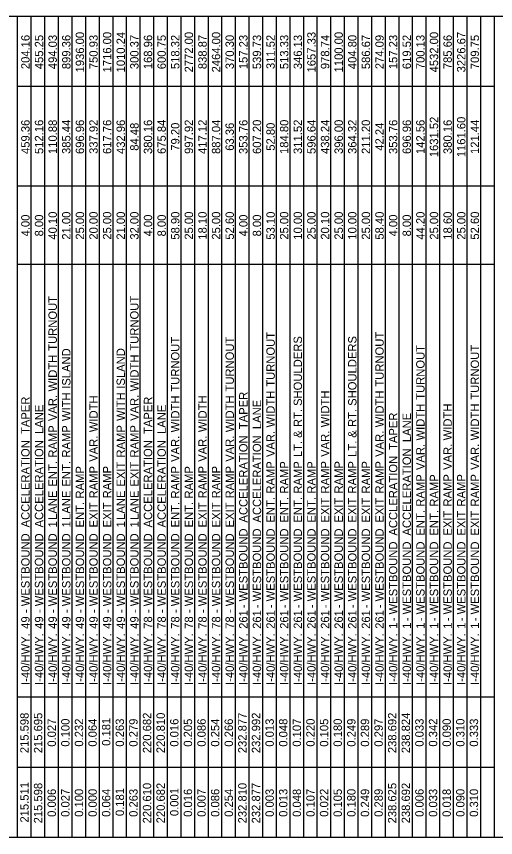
# Model space of a CAD drawing. Extents: x 2261867 to 2275370, y -3124789 to -3122260.
# Drawn here: x 2267289 to 2267632, y -3123394 to -3122807 of the extents above; entities that cross this region are included whole.
import ezdxf

# ---------------------------------------------------------------- set-up
doc = ezdxf.new("R2010")
doc.units = 0
doc.layers.add('Default', color=7, linetype='Continuous')

msp = doc.modelspace()

# ---------------------------------------------------------------- linework, layer by layer
at = {"layer": 'Default'}
for p, q in [((2268157.39, -3122806.82), (2267016.64, -3122806.82)), ((2268157.39, -3122806.82), (2267016.64, -3122806.82)), ((2267289.64, -3123394.26), (2267289.64, -3122806.82)), ((2267299.39, -3123394.26), (2267299.39, -3122806.82)), ((2267299.39, -3122857.03), (2267299.39, -3122806.82)), ((2267309.14, -3123394.26), (2267309.14, -3122806.82)), ((2267309.14, -3122857.03), (2267309.14, -3122806.82)), ((2267318.89, -3123394.26), (2267318.89, -3122806.82)), ((2267318.89, -3122857.03), (2267318.89, -3122806.82)), ((2267328.64, -3123394.26), (2267328.64, -3122806.82)), ((2267328.64, -3122857.03), (2267328.64, -3122806.82)), ((2267338.39, -3123394.26), (2267338.39, -3122806.82)), ((2267338.39, -3122857.03), (2267338.39, -3122806.82)), ((2267348.14, -3123394.26), (2267348.14, -3122806.82)), ((2267348.14, -3122857.03), (2267348.14, -3122806.82)), ((2267357.89, -3123394.26), (2267357.89, -3122806.82)), ((2267357.89, -3122857.03), (2267357.89, -3122806.82)), ((2267367.64, -3123394.26), (2267367.64, -3122806.82)), ((2267367.64, -3122857.03), (2267367.64, -3122806.82)), ((2267377.39, -3123394.26), (2267377.39, -3122806.82)), ((2267377.39, -3122857.03), (2267377.39, -3122806.82)), ((2267387.14, -3123394.26), (2267387.14, -3122806.82)), ((2267387.14, -3122857.03), (2267387.14, -3122806.82)), ((2267396.89, -3123394.26), (2267396.89, -3122806.82)), ((2267396.89, -3122857.03), (2267396.89, -3122806.82)), ((2267406.64, -3123394.26), (2267406.64, -3122806.82)), ((2267406.64, -3122857.03), (2267406.64, -3122806.82)), ((2267416.39, -3123394.26), (2267416.39, -3122806.82)), ((2267416.39, -3122857.03), (2267416.39, -3122806.82)), ((2267426.14, -3123394.26), (2267426.14, -3122806.82)), ((2267426.14, -3122857.03), (2267426.14, -3122806.82)), ((2267435.89, -3123394.26), (2267435.89, -3122806.82)), ((2267435.89, -3122857.03), (2267435.89, -3122806.82)), ((2267445.64, -3123394.26), (2267445.64, -3122806.82)), ((2267445.64, -3122857.03), (2267445.64, -3122806.82)), ((2267455.39, -3123394.26), (2267455.39, -3122806.82)), ((2267455.39, -3122857.03), (2267455.39, -3122806.82)), ((2267465.14, -3123394.26), (2267465.14, -3122806.82)), ((2267465.14, -3122857.03), (2267465.14, -3122806.82)), ((2267474.89, -3123394.26), (2267474.89, -3122806.82)), ((2267474.89, -3122857.03), (2267474.89, -3122806.82)), ((2267484.64, -3123394.26), (2267484.64, -3122806.82)), ((2267484.64, -3122857.03), (2267484.64, -3122806.82)), ((2267494.39, -3123394.26), (2267494.39, -3122806.82)), ((2267494.39, -3122857.03), (2267494.39, -3122806.82)), ((2267504.14, -3123394.26), (2267504.14, -3122806.82)), ((2267504.14, -3122857.03), (2267504.14, -3122806.82)), ((2267513.89, -3123394.26), (2267513.89, -3122806.82)), ((2267513.89, -3122857.03), (2267513.89, -3122806.82)), ((2267523.64, -3123394.26), (2267523.64, -3122806.82)), ((2267523.64, -3122857.03), (2267523.64, -3122806.82)), ((2267533.39, -3123394.26), (2267533.39, -3122806.82)), ((2267533.39, -3122857.03), (2267533.39, -3122806.82)), ((2267543.14, -3123394.26), (2267543.14, -3122806.82)), ((2267543.14, -3122857.03), (2267543.14, -3122806.82)), ((2267552.89, -3123394.26), (2267552.89, -3122806.82)), ((2267552.89, -3122857.03), (2267552.89, -3122806.82)), ((2267562.64, -3123394.26), (2267562.64, -3122806.82)), ((2267562.64, -3122857.03), (2267562.64, -3122806.82)), ((2267572.39, -3123394.26), (2267572.39, -3122806.82)), ((2267572.39, -3122857.03), (2267572.39, -3122806.82)), ((2267582.14, -3123394.26), (2267582.14, -3122806.82)), ((2267582.14, -3122857.03), (2267582.14, -3122806.82)), ((2267591.89, -3123394.26), (2267591.89, -3122806.82)), ((2267591.89, -3122857.03), (2267591.89, -3122806.82)), ((2267601.64, -3123394.26), (2267601.64, -3122806.82)), ((2267601.64, -3122857.03), (2267601.64, -3122806.82)), ((2267611.39, -3123394.26), (2267611.39, -3122806.82)), ((2267611.39, -3122857.03), (2267611.39, -3122806.82)), ((2267621.14, -3123394.26), (2267621.14, -3122806.82)), ((2267621.14, -3122857.03), (2267621.14, -3122806.82)), ((2267630.89, -3122857.03), (2267630.89, -3122806.82)), ((2267630.89, -3123394.26), (2267630.89, -3122806.82)), ((2267289.64, -3122928.21), (2267289.64, -3122857.03)), ((2267630.89, -3122857.03), (2267289.64, -3122857.03)), ((2267630.89, -3122857.03), (2267289.64, -3122857.03)), ((2267299.39, -3122928.21), (2267299.39, -3122857.03)), ((2267309.14, -3122928.21), (2267309.14, -3122857.03)), ((2267318.89, -3122928.21), (2267318.89, -3122857.03)), ((2267328.64, -3122928.21), (2267328.64, -3122857.03)), ((2267338.39, -3122928.21), (2267338.39, -3122857.03)), ((2267348.14, -3122928.21), (2267348.14, -3122857.03)), ((2267357.89, -3122928.21), (2267357.89, -3122857.03)), ((2267367.64, -3122928.21), (2267367.64, -3122857.03)), ((2267377.39, -3122928.21), (2267377.39, -3122857.03)), ((2267387.14, -3122928.21), (2267387.14, -3122857.03)), ((2267396.89, -3122928.21), (2267396.89, -3122857.03)), ((2267406.64, -3122928.21), (2267406.64, -3122857.03)), ((2267416.39, -3122928.21), (2267416.39, -3122857.03)), ((2267426.14, -3122928.21), (2267426.14, -3122857.03)), ((2267435.89, -3122928.21), (2267435.89, -3122857.03)), ((2267445.64, -3122928.21), (2267445.64, -3122857.03)), ((2267455.39, -3122928.21), (2267455.39, -3122857.03)), ((2267465.14, -3122928.21), (2267465.14, -3122857.03)), ((2267474.89, -3122928.21), (2267474.89, -3122857.03)), ((2267484.64, -3122928.21), (2267484.64, -3122857.03)), ((2267494.39, -3122928.21), (2267494.39, -3122857.03)), ((2267504.14, -3122928.21), (2267504.14, -3122857.03)), ((2267513.89, -3122928.21), (2267513.89, -3122857.03)), ((2267523.64, -3122928.21), (2267523.64, -3122857.03)), ((2267533.39, -3122928.21), (2267533.39, -3122857.03)), ((2267543.14, -3122928.21), (2267543.14, -3122857.03)), ((2267552.89, -3122928.21), (2267552.89, -3122857.03)), ((2267562.64, -3122928.21), (2267562.64, -3122857.03)), ((2267572.39, -3122928.21), (2267572.39, -3122857.03)), ((2267582.14, -3122984.27), (2267582.14, -3122857.03)), ((2267591.89, -3122984.27), (2267591.89, -3122857.03)), ((2267601.64, -3122984.27), (2267601.64, -3122857.03)), ((2267611.39, -3122984.27), (2267611.39, -3122857.03)), ((2267621.14, -3122984.27), (2267621.14, -3122857.03)), ((2267630.89, -3122984.27), (2267630.89, -3122857.03)), ((2267289.64, -3122984.27), (2267289.64, -3122928.21)), ((2267630.89, -3122928.21), (2267289.64, -3122928.21)), ((2267630.89, -3122928.21), (2267289.64, -3122928.21)), ((2267630.89, -3122984.27), (2267289.64, -3122984.27)), ((2267630.89, -3122984.27), (2267289.64, -3122984.27)), ((2267630.89, -3123394.26), (2267630.89, -3122984.27)), ((2267289.64, -3123394.26), (2267289.64, -3123293.83)), ((2267630.89, -3123293.83), (2267289.64, -3123293.83)), ((2267630.89, -3123293.83), (2267289.64, -3123293.83)), ((2267630.89, -3123344.05), (2267289.64, -3123344.05)), ((2267630.89, -3123344.05), (2267299.39, -3123344.05)), ((2268157.39, -3123394.26), (2267016.64, -3123394.26)), ((2268157.39, -3123394.26), (2267016.64, -3123394.26))]:
    msp.add_line(p, q, dxfattribs=at)

# ---------------------------------------------------------------- texts
for s, p in [('204.16', (2267298.19, -3122844.55)), ('455.25', (2267307.94, -3122844.57)), ('494.03', (2267317.69, -3122844.55)), ('899.36', (2267327.44, -3122844.55)), ('1936.00', (2267337.19, -3122846.87)), ('750.93', (2267346.94, -3122844.55)), ('1716.00', (2267356.69, -3122846.87)), ('1010.24', (2267366.44, -3122846.87)), ('300.37', (2267376.19, -3122844.55)), ('168.96', (2267385.94, -3122844.55)), ('600.75', (2267395.69, -3122844.57)), ('518.32', (2267405.44, -3122844.52)), ('2772.00', (2267415.19, -3122846.87)), ('838.87', (2267424.94, -3122844.55)), ('2464.00', (2267434.69, -3122846.87)), ('370.30', (2267444.44, -3122844.54)), ('157.23', (2267454.19, -3122844.55)), ('539.73', (2267463.94, -3122844.55)), ('311.52', (2267473.69, -3122844.52)), ('513.33', (2267483.44, -3122844.55)), ('346.13', (2267493.19, -3122844.55)), ('1657.33', (2267502.94, -3122846.88)), ('978.74', (2267512.69, -3122844.54)), ('1100.00', (2267522.44, -3122846.87)), ('404.80', (2267532.19, -3122844.54)), ('586.67', (2267541.94, -3122844.55)), ('274.09', (2267551.69, -3122844.56)), ('157.23', (2267561.44, -3122844.55)), ('619.52', (2267571.19, -3122844.52)), ('700.13', (2267580.94, -3122844.55)), ('4532.00', (2267590.69, -3122846.87)), ('785.66', (2267600.44, -3122844.55)), ('3226.67', (2267610.19, -3122846.88)), ('709.75', (2267619.94, -3122844.57)), ('459.36', (2267298.19, -3122905.25)), ('512.16', (2267307.94, -3122905.25)), ('110.88', (2267317.69, -3122905.25)), ('385.44', (2267327.44, -3122905.23)), ('696.96', (2267337.19, -3122905.25)), ('337.92', (2267346.94, -3122905.21)), ('617.76', (2267356.69, -3122905.25)), ('432.96', (2267366.44, -3122905.25)), ('380.16', (2267385.94, -3122905.25)), ('675.84', (2267395.69, -3122905.23)), ('997.92', (2267415.19, -3122905.21)), ('417.12', (2267424.94, -3122905.21)), ('887.04', (2267434.69, -3122905.23)), ('353.76', (2267454.19, -3122905.25)), ('607.20', (2267463.94, -3122905.23)), ('184.80', (2267483.44, -3122905.23)), ('311.52', (2267493.19, -3122905.21)), ('596.64', (2267502.94, -3122905.23)), ('438.24', (2267512.69, -3122905.23)), ('396.00', (2267522.44, -3122905.23)), ('364.32', (2267532.19, -3122905.21)), ('211.20', (2267541.94, -3122905.23)), ('353.76', (2267561.44, -3122905.25)), ('696.96', (2267571.19, -3122905.25)), ('142.56', (2267580.94, -3122905.25)), ('1631.52', (2267590.69, -3122907.54)), ('380.16', (2267600.44, -3122905.25)), ('1161.60', (2267610.19, -3122907.56)), ('121.44', (2267619.94, -3122905.23)), ('84.48', (2267376.19, -3122902.92)), ('79.20', (2267405.44, -3122902.9)), ('63.36', (2267444.44, -3122902.92)), ('52.80', (2267473.69, -3122902.9)), ('42.24', (2267551.69, -3122902.9)), ('40.10', (2267317.69, -3122966.52)), ('21.00', (2267327.44, -3122966.52)), ('25.00', (2267337.19, -3122966.52)), ('20.00', (2267346.94, -3122966.52)), ('25.00', (2267356.69, -3122966.52)), ('21.00', (2267366.44, -3122966.52)), ('32.00', (2267376.19, -3122966.52)), ('58.90', (2267405.44, -3122966.52)), ('25.00', (2267415.19, -3122966.52)), ('18.10', (2267424.94, -3122966.52)), ('25.00', (2267434.69, -3122966.52)), ('52.60', (2267444.44, -3122966.52)), ('53.10', (2267473.69, -3122966.52)), ('25.00', (2267483.44, -3122966.52)), ('10.00', (2267493.19, -3122966.52)), ('25.00', (2267502.94, -3122966.52)), ('20.10', (2267512.69, -3122966.52)), ('25.00', (2267522.44, -3122966.52)), ('10.00', (2267532.19, -3122966.52)), ('25.00', (2267541.94, -3122966.52)), ('58.40', (2267551.69, -3122966.52)), ('44.20', (2267580.94, -3122966.52)), ('25.00', (2267590.69, -3122966.52)), ('18.60', (2267600.44, -3122966.52)), ('25.00', (2267610.19, -3122966.52)), ('52.60', (2267619.94, -3122966.52)), ('4.00', (2267298.19, -3122964.19)), ('8.00', (2267307.94, -3122964.19)), ('4.00', (2267385.94, -3122964.19)), ('8.00', (2267395.69, -3122964.19)), ('4.00', (2267454.19, -3122964.19)), ('8.00', (2267463.94, -3122964.19)), ('4.00', (2267561.44, -3122964.19)), ('8.00', (2267571.19, -3122964.19)), (' TURNOUT', (2267317.69, -3123048.23)), (' TURNOUT', (2267376.19, -3123048.13)), (' TURNOUT', (2267473.69, -3123073.97)), (' TURNOUT', (2267551.69, -3123073.87)), (' TURNOUT', (2267405.44, -3123077.46)), (' TURNOUT', (2267444.44, -3123077.36)), (' SHOULDERS', (2267493.19, -3123087.72)), (' SHOULDERS', (2267532.19, -3123087.62)), (' ISLAND', (2267327.44, -3123075.45)), (' ISLAND', (2267366.44, -3123075.35)), (' TURNOUT', (2267580.94, -3123083.29)), (' TURNOUT', (2267619.94, -3123083.19)), (' WIDTH', (2267317.69, -3123077.35)), (' WIDTH', (2267376.19, -3123077.25)), (' TAPER', (2267454.19, -3123104.27)), (' WIDTH', (2267473.69, -3123103.09)), (' WIDTH', (2267512.69, -3123102.99)), (' WIDTH', (2267551.69, -3123102.99)), (' TAPER', (2267298.19, -3123107.76)), (' VAR.', (2267317.69, -3123098.52)), (' WITH', (2267327.44, -3123098.52)), (' WIDTH', (2267346.94, -3123106.48)), (' WITH', (2267366.44, -3123098.42)), (' VAR.', (2267376.19, -3123098.42)), (' TAPER', (2267385.94, -3123107.76)), (' WIDTH', (2267405.44, -3123106.58)), (' WIDTH', (2267424.94, -3123106.48)), (' WIDTH', (2267444.44, -3123106.48)), (' LANE', (2267463.94, -3123104.27)), (' LANE', (2267307.94, -3123107.76)), (' LANE', (2267395.69, -3123107.76)), (' WIDTH', (2267580.94, -3123112.41)), (' WIDTH', (2267600.44, -3123112.31)), (' WIDTH', (2267619.94, -3123112.31)), (' RT.', (2267493.19, -3123102.82)), (' RT.', (2267532.19, -3123102.72)), (' TAPER', (2267561.44, -3123119.19)), (' LANE', (2267571.19, -3123113.59)), (' RAMP', (2267317.69, -3123124.7)), (' RAMP', (2267327.44, -3123124.7)), (' RAMP', (2267366.44, -3123124.6)), (' RAMP', (2267376.19, -3123124.6)), (' VAR.', (2267473.69, -3123124.26)), (' &', (2267493.19, -3123110.55)), (' VAR.', (2267512.69, -3123124.16)), (' &', (2267532.19, -3123110.45)), (' VAR.', (2267551.69, -3123124.16)), (' ACCELERATION', (2267298.19, -3123174.63)), (' ACCELERATION', (2267307.94, -3123174.63)), (' VAR.', (2267346.94, -3123127.65)), (' ACCELERATION', (2267385.94, -3123174.63)), (' ACCELERATION', (2267395.69, -3123174.63)), (' VAR.', (2267405.44, -3123127.75)), (' VAR.', (2267424.94, -3123127.65)), (' VAR.', (2267444.44, -3123127.65)), (' ACCELERATION', (2267454.19, -3123171.14)), (' ACCELERATION', (2267463.94, -3123171.14)), (' LT.', (2267493.19, -3123124.26)), (' LT.', (2267532.19, -3123124.16)), (' ACCELERATION', (2267571.19, -3123180.46)), (' VAR.', (2267580.94, -3123133.58)), (' VAR.', (2267600.44, -3123133.48)), (' VAR.', (2267619.94, -3123133.48)), (' ACCLERATION', (2267561.44, -3123180.46)), (' ENT.', (2267317.69, -3123145.4)), (' ENT.', (2267327.44, -3123145.4)), (' RAMP', (2267337.19, -3123153.93)), (' RAMP', (2267346.94, -3123153.83)), (' RAMP', (2267356.69, -3123153.83)), (' EXIT', (2267366.44, -3123145.4)), (' EXIT', (2267376.19, -3123145.4)), (' RAMP', (2267405.44, -3123153.93)), (' RAMP', (2267415.19, -3123153.93)), (' RAMP', (2267424.94, -3123153.83)), (' RAMP', (2267434.69, -3123153.83)), (' RAMP', (2267444.44, -3123153.83)), (' RAMP', (2267473.69, -3123150.44)), (' RAMP', (2267483.44, -3123150.44)), (' RAMP', (2267493.19, -3123150.44)), (' RAMP', (2267502.94, -3123150.44)), (' RAMP', (2267512.69, -3123150.34)), (' RAMP', (2267522.44, -3123150.34)), (' RAMP', (2267532.19, -3123150.34)), (' RAMP', (2267541.94, -3123150.34)), (' RAMP', (2267551.69, -3123150.34)), (' RAMP', (2267580.94, -3123159.76)), (' RAMP', (2267590.69, -3123159.76)), (' RAMP', (2267600.44, -3123159.66)), (' RAMP', (2267610.19, -3123159.66)), (' RAMP', (2267619.94, -3123159.66)), (' LANE', (2267317.69, -3123169.18)), (' LANE', (2267327.44, -3123169.18)), (' LANE', (2267366.44, -3123169.18)), (' LANE', (2267376.19, -3123169.18)), (' ENT.', (2267473.69, -3123171.14)), (' ENT.', (2267483.44, -3123171.14)), (' ENT.', (2267493.19, -3123171.14)), (' ENT.', (2267502.94, -3123171.14)), (' EXIT', (2267512.69, -3123171.14)), (' EXIT', (2267522.44, -3123171.14)), (' EXIT', (2267532.19, -3123171.14)), (' EXIT', (2267541.94, -3123171.14)), (' EXIT', (2267551.69, -3123171.14)), (' ENT.', (2267337.19, -3123174.63)), (' EXIT', (2267346.94, -3123174.63)), (' EXIT', (2267356.69, -3123174.63)), (' ENT.', (2267405.44, -3123174.63)), (' ENT.', (2267415.19, -3123174.63)), (' EXIT', (2267424.94, -3123174.63)), (' EXIT', (2267434.69, -3123174.63)), (' EXIT', (2267444.44, -3123174.63)), (' ENT.', (2267580.94, -3123180.46)), (' ENT.', (2267590.69, -3123180.46)), (' EXIT', (2267600.44, -3123180.46)), (' EXIT', (2267610.19, -3123180.46)), (' EXIT', (2267619.94, -3123180.46)), (' 1', (2267317.69, -3123174.63)), (' 1', (2267327.44, -3123174.63)), (' 1', (2267366.44, -3123174.63)), (' 1', (2267376.19, -3123174.63)), (' WESTBOUND', (2267454.19, -3123227.51)), (' WESTBOUND', (2267463.94, -3123227.51)), (' WESTBOUND', (2267473.69, -3123227.51)), (' WESTBOUND', (2267483.44, -3123227.51)), (' WESTBOUND', (2267493.19, -3123227.51)), (' WESTBOUND', (2267502.94, -3123227.51)), (' WESTBOUND', (2267512.69, -3123227.51)), (' WESTBOUND', (2267522.44, -3123227.51)), (' WESTBOUND', (2267532.19, -3123227.51)), (' WESTBOUND', (2267541.94, -3123227.51)), (' WESTBOUND', (2267551.69, -3123227.51)), (' WESTBOUND', (2267298.19, -3123231)), (' WESTBOUND', (2267307.94, -3123231)), (' WESTBOUND', (2267317.69, -3123231)), (' WESTBOUND', (2267327.44, -3123231)), (' WESTBOUND', (2267337.19, -3123231)), (' WESTBOUND', (2267346.94, -3123231)), (' WESTBOUND', (2267356.69, -3123231)), (' WESTBOUND', (2267366.44, -3123231)), (' WESTBOUND', (2267376.19, -3123231)), (' WESTBOUND', (2267385.94, -3123231)), (' WESTBOUND', (2267395.69, -3123231)), (' WESTBOUND', (2267405.44, -3123231)), (' WESTBOUND', (2267415.19, -3123231)), (' WESTBOUND', (2267424.94, -3123231)), (' WESTBOUND', (2267434.69, -3123231)), (' WESTBOUND', (2267444.44, -3123231)), (' WESTBOUND', (2267561.44, -3123236.83)), (' WESTBOUND', (2267571.19, -3123236.83)), (' WESTBOUND', (2267580.94, -3123236.83)), (' WESTBOUND', (2267590.69, -3123236.83)), (' WESTBOUND', (2267600.44, -3123236.83)), (' WESTBOUND', (2267610.19, -3123236.83)), (' WESTBOUND', (2267619.94, -3123236.83)), (' -', (2267454.19, -3123232.37)), (' -', (2267463.94, -3123232.37)), (' -', (2267473.69, -3123232.37)), (' -', (2267483.44, -3123232.37)), (' -', (2267493.19, -3123232.37)), (' -', (2267502.94, -3123232.37)), (' -', (2267512.69, -3123232.37)), (' -', (2267522.44, -3123232.37)), (' -', (2267532.19, -3123232.37)), (' -', (2267541.94, -3123232.37)), (' -', (2267551.69, -3123232.37)), (' -', (2267298.19, -3123235.86)), (' -', (2267307.94, -3123235.86)), (' -', (2267317.69, -3123235.86)), (' -', (2267327.44, -3123235.86)), (' -', (2267337.19, -3123235.86)), (' -', (2267346.94, -3123235.86)), (' -', (2267356.69, -3123235.86)), (' -', (2267366.44, -3123235.86)), (' -', (2267376.19, -3123235.86)), (' -', (2267385.94, -3123235.86)), (' -', (2267395.69, -3123235.86)), (' -', (2267405.44, -3123235.86)), (' -', (2267415.19, -3123235.86)), (' -', (2267424.94, -3123235.86)), (' -', (2267434.69, -3123235.86)), (' -', (2267444.44, -3123235.86)), (' 261', (2267454.19, -3123247.14)), (' 261', (2267463.94, -3123247.14)), (' 261', (2267473.69, -3123247.14)), (' 261', (2267483.44, -3123247.14)), (' 261', (2267493.19, -3123247.14)), (' 261', (2267502.94, -3123247.14)), (' 261', (2267512.69, -3123247.14)), (' 261', (2267522.44, -3123247.14)), (' 261', (2267532.19, -3123247.14)), (' 261', (2267541.94, -3123247.14)), (' 261', (2267551.69, -3123247.14)), (' 49', (2267298.19, -3123247.14)), (' 49', (2267307.94, -3123247.14)), (' 49', (2267317.69, -3123247.14)), (' 49', (2267327.44, -3123247.14)), (' 49', (2267337.19, -3123247.14)), (' 49', (2267346.94, -3123247.14)), (' 49', (2267356.69, -3123247.14)), (' 49', (2267366.44, -3123247.14)), (' 49', (2267376.19, -3123247.14)), (' 78', (2267385.94, -3123247.14)), (' 78', (2267395.69, -3123247.14)), (' 78', (2267405.44, -3123247.14)), (' 78', (2267415.19, -3123247.14)), (' 78', (2267424.94, -3123247.14)), (' 78', (2267434.69, -3123247.14)), (' 78', (2267444.44, -3123247.14)), (' -', (2267561.44, -3123241.69)), (' -', (2267571.19, -3123241.69)), (' -', (2267580.94, -3123241.69)), (' -', (2267590.69, -3123241.69)), (' -', (2267600.44, -3123241.69)), (' -', (2267610.19, -3123241.69)), (' -', (2267619.94, -3123241.69)), (' 1', (2267561.44, -3123247.14)), (' 1', (2267571.19, -3123247.14)), (' 1', (2267580.94, -3123247.14)), (' 1', (2267590.69, -3123247.14)), (' 1', (2267600.44, -3123247.14)), (' 1', (2267610.19, -3123247.14)), (' 1', (2267619.94, -3123247.14)), ('I-40/HWY.', (2267298.19, -3123285.06)), ('I-40/HWY.', (2267307.94, -3123285.06)), ('I-40/HWY.', (2267317.69, -3123285.06)), ('I-40/HWY.', (2267327.44, -3123285.06)), ('I-40/HWY.', (2267337.19, -3123285.06)), ('I-40/HWY.', (2267346.94, -3123285.06)), ('I-40/HWY.', (2267356.69, -3123285.06)), ('I-40/HWY.', (2267366.44, -3123285.06)), ('I-40/HWY.', (2267376.19, -3123285.06)), ('I-40/HWY.', (2267385.94, -3123285.06)), ('I-40/HWY.', (2267395.69, -3123285.06)), ('I-40/HWY.', (2267405.44, -3123285.06)), ('I-40/HWY.', (2267415.19, -3123285.06)), ('I-40/HWY.', (2267424.94, -3123285.06)), ('I-40/HWY.', (2267434.69, -3123285.06)), ('I-40/HWY.', (2267444.44, -3123285.06)), ('I-40/HWY.', (2267454.19, -3123285.06)), ('I-40/HWY.', (2267463.94, -3123285.06)), ('I-40/HWY.', (2267473.69, -3123285.06)), ('I-40/HWY.', (2267483.44, -3123285.06)), ('I-40/HWY.', (2267493.19, -3123285.06)), ('I-40/HWY.', (2267502.94, -3123285.06)), ('I-40/HWY.', (2267512.69, -3123285.06)), ('I-40/HWY.', (2267522.44, -3123285.06)), ('I-40/HWY.', (2267532.19, -3123285.06)), ('I-40/HWY.', (2267541.94, -3123285.06)), ('I-40/HWY.', (2267551.69, -3123285.06)), ('I-40/HWY.', (2267561.44, -3123285.06)), ('I-40/HWY.', (2267571.19, -3123285.06)), ('I-40/HWY.', (2267580.94, -3123285.06)), ('I-40/HWY.', (2267590.69, -3123285.06)), ('I-40/HWY.', (2267600.44, -3123285.06)), ('I-40/HWY.', (2267610.19, -3123285.06)), ('I-40/HWY.', (2267619.94, -3123285.06)), ('215.598', (2267297.51, -3123333.9)), ('215.695', (2267307.26, -3123333.92)), ('220.682', (2267385.26, -3123333.86)), ('220.810', (2267395.01, -3123333.88)), ('232.877', (2267453.51, -3123333.89)), ('232.992', (2267463.26, -3123333.86)), ('238.692', (2267560.76, -3123333.86)), ('238.824', (2267570.51, -3123333.88)), ('0.027', (2267317.01, -3123329.23)), ('0.100', (2267326.76, -3123329.22)), ('0.232', (2267336.51, -3123329.2)), ('0.064', (2267346.26, -3123329.22)), ('0.181', (2267356.01, -3123328.65)), ('0.263', (2267365.76, -3123329.23)), ('0.279', (2267375.51, -3123329.24)), ('0.016', (2267404.76, -3123329.23)), ('0.205', (2267414.51, -3123329.26)), ('0.086', (2267424.26, -3123329.23)), ('0.254', (2267434.01, -3123329.22)), ('0.266', (2267443.76, -3123329.23)), ('0.013', (2267473.01, -3123329.23)), ('0.048', (2267482.76, -3123329.24)), ('0.107', (2267492.51, -3123329.23)), ('0.220', (2267502.26, -3123329.22)), ('0.105', (2267512.01, -3123329.26)), ('0.180', (2267521.76, -3123329.22)), ('0.249', (2267531.51, -3123329.24)), ('0.289', (2267541.26, -3123329.24)), ('0.297', (2267551.01, -3123329.23)), ('0.033', (2267580.26, -3123329.23)), ('0.342', (2267590.01, -3123329.2)), ('0.090', (2267599.76, -3123329.22)), ('0.310', (2267609.51, -3123329.22)), ('0.333', (2267619.26, -3123329.23)), ('215.511', (2267297.51, -3123383.53)), ('215.598', (2267307.26, -3123384.11)), ('220.610', (2267385.26, -3123384.1)), ('220.682', (2267395.01, -3123384.07)), ('232.810', (2267453.51, -3123384.1)), ('232.877', (2267463.26, -3123384.11)), ('238.625', (2267560.76, -3123384.13)), ('238.692', (2267570.51, -3123384.07)), ('0.006', (2267317.01, -3123379.45)), ('0.027', (2267326.76, -3123379.45)), ('0.100', (2267336.51, -3123379.44)), ('0.000', (2267346.26, -3123379.44)), ('0.064', (2267356.01, -3123379.43)), ('0.181', (2267365.76, -3123378.87)), ('0.263', (2267375.51, -3123379.45)), ('0.001', (2267404.76, -3123378.87)), ('0.016', (2267414.51, -3123379.45)), ('0.007', (2267424.26, -3123379.45)), ('0.086', (2267434.01, -3123379.45)), ('0.254', (2267443.76, -3123379.43)), ('0.003', (2267473.01, -3123379.45)), ('0.013', (2267482.76, -3123379.45)), ('0.048', (2267492.51, -3123379.45)), ('0.107', (2267502.26, -3123379.45)), ('0.022', (2267512.01, -3123379.41)), ('0.105', (2267521.76, -3123379.47)), ('0.180', (2267531.51, -3123379.44)), ('0.249', (2267541.26, -3123379.45)), ('0.289', (2267551.01, -3123379.45)), ('0.006', (2267580.26, -3123379.45)), ('0.033', (2267590.01, -3123379.45)), ('0.018', (2267599.76, -3123379.45)), ('0.090', (2267609.51, -3123379.44)), ('0.310', (2267619.26, -3123379.44))]:
    msp.add_text(s, height=6, rotation=90, dxfattribs=at).set_placement(p)

doc.saveas('drawing.dxf')
